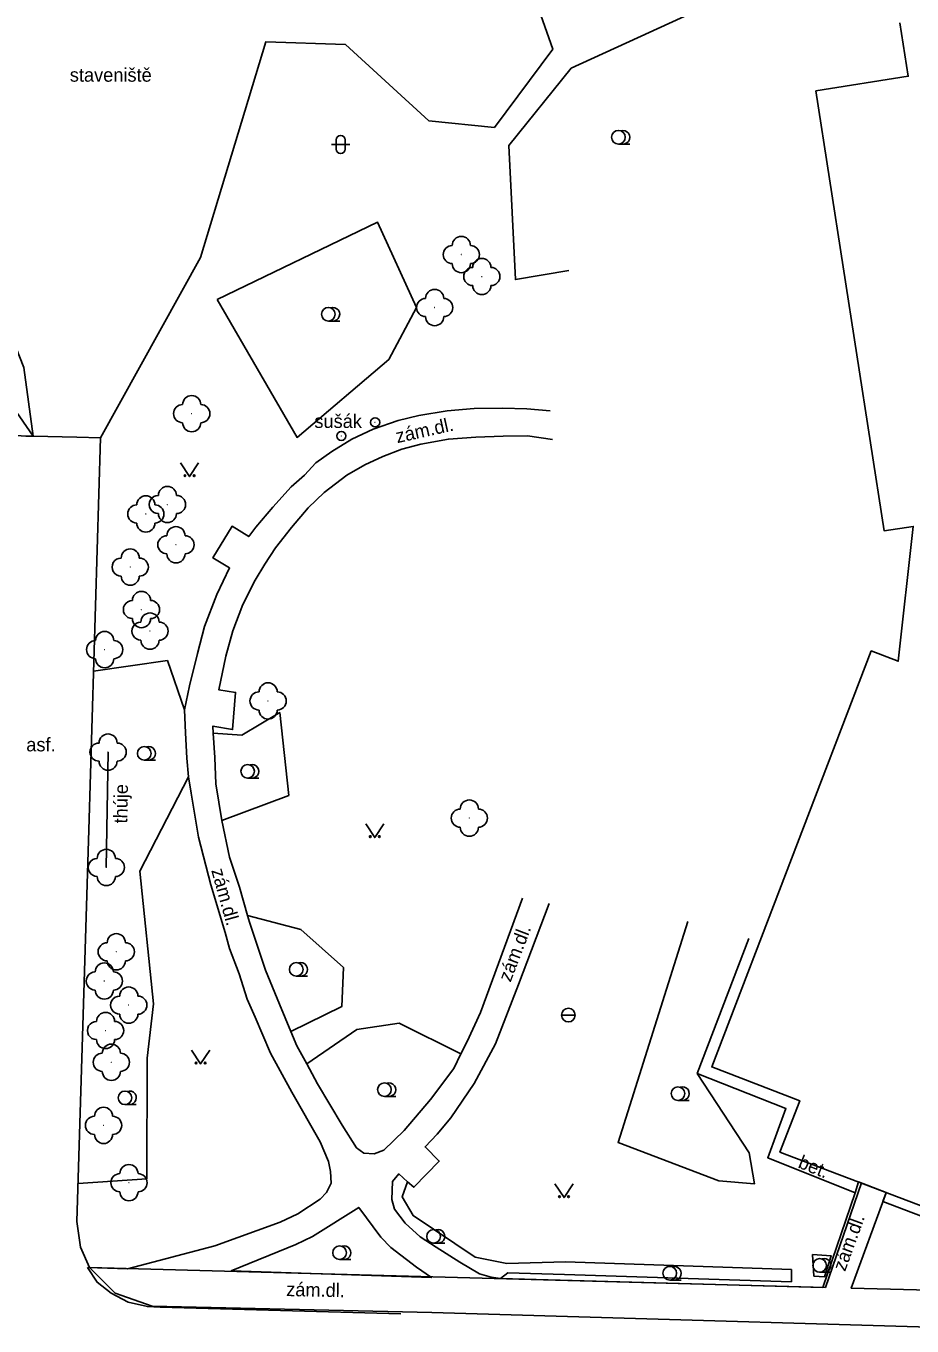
# Model space of a CAD drawing. Extents: x -584400 to -581602, y -1210894 to -1208793.
# Drawn here: x -582747.8 to -582698.9, y -1209957.3 to -1209885.6 of the extents above; entities that cross this region are included whole.
import ezdxf

# ---------------------------------------------------------------- set-up
doc = ezdxf.new("R2010")
doc.units = 0
for name, color, linetype in [('BUDOVY_MĚŘ', 7, 'Continuous'), ('POMOC_POPIS', 7, 'Continuous'), ('ROZHRANÍ_PLOCH', 7, 'Continuous'), ('VÝŠKOPIS', 7, 'Continuous'), ('ZELEŇ', 7, 'Continuous'), ('ZN_DOPLŇKOVÉ', 7, 'Continuous'), ('ZN_KULTUR', 7, 'Continuous')]:
    doc.layers.add(name, color=color, linetype=linetype)

msp = doc.modelspace()

# ---------------------------------------------------------------- linework, layer by layer
at = {"layer": 'BUDOVY_MĚŘ'}
for points in [[(-582688.59, -1209883.71), (-582688.07, -1209886.96), (-582683.44, -1209886.21), (-582679.67, -1209910.15), (-582680.11, -1209910.22), (-582679.82, -1209913.58), (-582679.75, -1209916.25), (-582680.55, -1209916.44), (-582681.08, -1209921.35), (-582680.32, -1209921.67), (-582680.94, -1209924.3), (-582681.99, -1209927.46), (-582681.57, -1209927.62), (-582690.3, -1209950.23), (-582694.69, -1209948.54), (-582695.81, -1209951.64), (-582706.2, -1209947.68), (-582705.11, -1209944.85), (-582709.96, -1209942.99), (-582701.17, -1209920.05), (-582699.68, -1209920.62), (-582698.85, -1209913.19), (-582700.45, -1209913.44), (-582704.22, -1209889.17)], [(-582704.22, -1209889.17), (-582699.13, -1209888.37), (-582699.59, -1209885.42)]]:
    msp.add_lwpolyline(points, dxfattribs=at)
at = {"layer": 'ROZHRANÍ_PLOCH'}
for points in [[(-582743.64, -1209908.31), (-582738.14, -1209898.36), (-582734.53, -1209886.47), (-582730.14, -1209886.62), (-582725.56, -1209890.82), (-582721.94, -1209891.19), (-582718.71, -1209886.88), (-582720.59, -1209881.55), (-582720.32, -1209873.3), (-582716.2, -1209870.3), (-582710.56, -1209867.68), (-582702.54, -1209865.54), (-582699, -1209870.36)], [(-582757.47, -1209885.68), (-582753.16, -1209892.91), (-582749.85, -1209899.43), (-582747.87, -1209904.42), (-582747.36, -1209908.22)], [(-582718.87, -1209906.82), (-582720.15, -1209906.71), (-582721.49, -1209906.66), (-582723.05, -1209906.68), (-582724.54, -1209906.82), (-582726.1, -1209907.08), (-582727.24, -1209907.34), (-582728.62, -1209907.83), (-582729.8, -1209908.37), (-582730.89, -1209909.05), (-582731.78, -1209909.69), (-582732.4, -1209910.37), (-582733.14, -1209911), (-582734.15, -1209912.13), (-582735.09, -1209913.22), (-582735.48, -1209913.75), (-582736.4, -1209913.18), (-582737.45, -1209914.92), (-582736.53, -1209915.48), (-582737.23, -1209916.94), (-582737.91, -1209918.7), (-582738.3, -1209920.2), (-582738.75, -1209921.98), (-582739.01, -1209923.3)], [(-582747.36, -1209908.22), (-582747.77, -1209908.21), (-582749.09, -1209908.12), (-582749.33, -1209915.59)], [(-582744.95, -1209908.27), (-582747.36, -1209908.22)], [(-582744.3, -1209929.91), (-582743.64, -1209908.31), (-582744.95, -1209908.27)], [(-582737.43, -1209924.59), (-582737.45, -1209924.2), (-582736.37, -1209924.39), (-582736.2, -1209922.34), (-582737.12, -1209922.2), (-582736.74, -1209920.35), (-582736.35, -1209918.94), (-582735.8, -1209917.5), (-582735.13, -1209916.16), (-582734.59, -1209915.27), (-582734, -1209914.37), (-582733.12, -1209913.25), (-582732.2, -1209912.16), (-582731.32, -1209911.31), (-582730.08, -1209910.37), (-582729.08, -1209909.79), (-582728.08, -1209909.33), (-582727.04, -1209908.93), (-582725.99, -1209908.66), (-582724.47, -1209908.37), (-582722.97, -1209908.26), (-582721.46, -1209908.22), (-582720.12, -1209908.19), (-582718.73, -1209908.39)], [(-582738.8, -1209926.99), (-582738.89, -1209925.97), (-582738.96, -1209924.57), (-582739.01, -1209923.3)], [(-582736.97, -1209929.41), (-582737.3, -1209927.38), (-582737.34, -1209925.92), (-582737.43, -1209924.59)], [(-582744.36, -1209954.05), (-582742.16, -1209954.11), (-582737.35, -1209952.85), (-582733.75, -1209951.54), (-582732.78, -1209951.08), (-582731.55, -1209950.27), (-582731.19, -1209949.91), (-582730.94, -1209949.4), (-582730.97, -1209948.75), (-582731.09, -1209948.21), (-582731.55, -1209947.11), (-582733.11, -1209944.38), (-582734.27, -1209942.23), (-582735.13, -1209940.24), (-582735.56, -1209939.26), (-582736.01, -1209937.85), (-582736.54, -1209936.45), (-582736.78, -1209935.58), (-582737.56, -1209932.94), (-582738.25, -1209930.32), (-582738.65, -1209927.89), (-582738.8, -1209926.99)], [(-582735.55, -1209934.63), (-582735.98, -1209933.08), (-582736.54, -1209931.42), (-582736.97, -1209929.41)], [(-582744.95, -1209951.51), (-582744.3, -1209929.91)], [(-582726.72, -1209949.32), (-582726.37, -1209949.62), (-582724.98, -1209948.18), (-582725.76, -1209947.4), (-582725.09, -1209946.69), (-582724.33, -1209945.79), (-582723.06, -1209943.9), (-582721.87, -1209941.71), (-582720.61, -1209938.44), (-582718.92, -1209933.97)], [(-582720.38, -1209933.68), (-582722.71, -1209939.99), (-582723.44, -1209941.58), (-582723.78, -1209942.26)], [(-582733.15, -1209941.04), (-582733.79, -1209939.53), (-582734.56, -1209937.65), (-582735.44, -1209935.01), (-582735.55, -1209934.63)], [(-582710.77, -1209943.35), (-582707.91, -1209935.91)], [(-582732.28, -1209942.82), (-582732.82, -1209941.83), (-582733.15, -1209941.04)], [(-582723.78, -1209942.26), (-582724.18, -1209943.07), (-582725.46, -1209944.79), (-582726.92, -1209946.5), (-582728.04, -1209947.58), (-582728.57, -1209947.78), (-582729.13, -1209947.75), (-582729.54, -1209947.44), (-582730.33, -1209946.2), (-582731.68, -1209943.91), (-582732.28, -1209942.82)], [(-582702.06, -1209949.93), (-582706.87, -1209947.99), (-582705.87, -1209945.27), (-582710.77, -1209943.35)], [(-582721.61, -1209954.66), (-582722.11, -1209954.57), (-582722.76, -1209954.39), (-582723.84, -1209953.75), (-582725.15, -1209952.92), (-582726.02, -1209952.35), (-582726.85, -1209951.6), (-582727.44, -1209950.83), (-582727.6, -1209950.3), (-582727.56, -1209949.31), (-582727.21, -1209948.89), (-582726.72, -1209949.32)], [(-582701.71, -1209949.37), (-582703.69, -1209955.14), (-582744.25, -1209954.04)], [(-582702.06, -1209949.93), (-582701.86, -1209949.33)], [(-582702.06, -1209949.93), (-582703.83, -1209955.14), (-582721.61, -1209954.66)], [(-582684.25, -1209955.64), (-582702.27, -1209955.19), (-582700.35, -1209949.93)], [(-582700.53, -1209950.41), (-582700.35, -1209949.91)], [(-582695.46, -1209952.34), (-582700.53, -1209950.41)], [(-582736.45, -1209954.23), (-582732.89, -1209952.77), (-582731.96, -1209952.34), (-582729.41, -1209950.73), (-582728.2, -1209952.37), (-582727.64, -1209952.94), (-582726.24, -1209954.02), (-582725.41, -1209954.6), (-582736.45, -1209954.23)], [(-582740.8, -1209956.17), (-582742.84, -1209955.46), (-582744.25, -1209954.04), (-582744.75, -1209952.92), (-582744.95, -1209951.51)], [(-582727.09, -1209956.6), (-582740.36, -1209956.23), (-582741.06, -1209956.2), (-582742.13, -1209955.95), (-582743.06, -1209955.46), (-582743.84, -1209954.86), (-582744.36, -1209954.05)], [(-582740.8, -1209956.17), (-582725.38, -1209956.53), (-582689.21, -1209957.59), (-582687.98, -1209957.62), (-582671.03, -1209958.14)]]:
    msp.add_lwpolyline(points, dxfattribs=at)
at = {"layer": 'VÝŠKOPIS'}
msp.add_lwpolyline([(-582755.21, -1209894.05), (-582754.02, -1209896.75), (-582750.32, -1209903.94), (-582747.36, -1209908.22)], dxfattribs=at)
at = {"layer": 'ZELEŇ'}
for points in [[(-582709.1, -1209883.98), (-582717.7, -1209887.93), (-582721.14, -1209892.18), (-582720.78, -1209899.58), (-582717.84, -1209899.08)], [(-582737.22, -1209900.68), (-582732.81, -1209908.28), (-582727.76, -1209903.98), (-582726.24, -1209901.12), (-582728.38, -1209896.42), (-582737.22, -1209900.68)], [(-582744.03, -1209921.16), (-582739.96, -1209920.58), (-582739.01, -1209923.3)], [(-582736.97, -1209929.41), (-582733.27, -1209928.02), (-582733.77, -1209923.45), (-582735.85, -1209924.7), (-582737.43, -1209924.59)], [(-582743.33, -1209931.99), (-582743.23, -1209925.63)], [(-582738.8, -1209926.99), (-582741.48, -1209932.2), (-582740.72, -1209939.5), (-582741.07, -1209942.51), (-582741.1, -1209949.15), (-582744.88, -1209949.41)], [(-582735.55, -1209934.63), (-582732.61, -1209935.41), (-582730.26, -1209937.5), (-582730.35, -1209939.66), (-582733.15, -1209941.04)], [(-582711.28, -1209934.97), (-582715.12, -1209947.16), (-582709.57, -1209949.27), (-582707.61, -1209949.44), (-582707.89, -1209947.73), (-582710.77, -1209943.35)], [(-582732.28, -1209942.82), (-582729.52, -1209940.93), (-582727.18, -1209940.58), (-582723.78, -1209942.26)], [(-582726.72, -1209949.32), (-582727.03, -1209950.15), (-582726.41, -1209951.18), (-582722.99, -1209953.48), (-582721.25, -1209953.82), (-582718.02, -1209953.73), (-582705.57, -1209954.16), (-582705.57, -1209954.83), (-582718.08, -1209954.43), (-582721.19, -1209954.33), (-582721.61, -1209954.66)], [(-582704.4, -1209953.32), (-582704.33, -1209954.52), (-582703.75, -1209954.56), (-582703.37, -1209953.41), (-582704.4, -1209953.32)]]:
    msp.add_lwpolyline(points, dxfattribs=at)
for centre in [(-582723.76, -1209898.2), (-582722.63, -1209899.41), (-582725.23, -1209901.12), (-582738.62, -1209906.97), (-582741.15, -1209912.5), (-582739.96, -1209911.98), (-582739.49, -1209914.2), (-582742.01, -1209915.43), (-582741.39, -1209917.77), (-582740.92, -1209918.96), (-582743.42, -1209919.98), (-582734.41, -1209922.81), (-582743.23, -1209925.63), (-582723.32, -1209929.27), (-582743.33, -1209931.99), (-582742.78, -1209936.64), (-582743.44, -1209938.25), (-582742.09, -1209939.58), (-582743.37, -1209940.98), (-582743.05, -1209942.73), (-582743.48, -1209946.21), (-582742.08, -1209949.37)]:
    msp.add_circle(centre, 0.0005, dxfattribs=at)
for centre, start, end in [((-582723.76, -1209897.7), 0, 179.99999), ((-582724.26, -1209898.2), 89.99999, 269.99999), ((-582723.26, -1209898.2), 270, 89.99999), ((-582723.76, -1209898.7), 179.99999, 359.99999), ((-582723.13, -1209899.41), 89.99999, 269.99999), ((-582722.63, -1209898.91), 0, 179.99999), ((-582722.13, -1209899.41), 270, 89.99999), ((-582725.23, -1209900.62), 360, 179.99999), ((-582722.63, -1209899.91), 179.99999, 359.99999), ((-582725.73, -1209901.12), 90, 269.99999), ((-582724.73, -1209901.12), 270, 90), ((-582725.23, -1209901.62), 180, 360), ((-582738.62, -1209906.47), 0, 179.99999), ((-582739.12, -1209906.97), 89.99999, 269.99999), ((-582738.12, -1209906.97), 270, 89.99999), ((-582738.62, -1209907.47), 179.99999, 359.99999), ((-582739.96, -1209911.48), 359.99998, 179.99998), ((-582741.15, -1209912), 0, 179.99999), ((-582740.46, -1209911.98), 89.99998, 269.99998), ((-582739.46, -1209911.98), 269.99998, 89.99997), ((-582741.65, -1209912.5), 89.99999, 269.99999), ((-582740.65, -1209912.5), 270, 89.99999), ((-582739.96, -1209912.48), 179.99998, 359.99997), ((-582741.15, -1209913), 179.99999, 359.99999), ((-582739.49, -1209913.7), 360, 179.99999), ((-582739.99, -1209914.2), 90, 269.99999), ((-582738.99, -1209914.2), 270, 90), ((-582742.01, -1209914.93), 359.99998, 179.99998), ((-582739.49, -1209914.7), 180, 360), ((-582742.51, -1209915.43), 89.99998, 269.99998), ((-582741.51, -1209915.43), 269.99998, 89.99997), ((-582742.01, -1209915.93), 179.99998, 359.99997), ((-582741.39, -1209917.27), 359.99998, 179.99998), ((-582741.89, -1209917.77), 89.99998, 269.99998), ((-582740.89, -1209917.77), 269.99998, 89.99997), ((-582741.39, -1209918.27), 179.99998, 359.99997), ((-582740.92, -1209918.46), 359.99998, 179.99998), ((-582743.42, -1209919.48), 360, 179.99999), ((-582741.42, -1209918.96), 89.99998, 269.99998), ((-582740.42, -1209918.96), 269.99998, 89.99997), ((-582743.92, -1209919.98), 90, 269.99999), ((-582742.92, -1209919.98), 270, 90), ((-582740.92, -1209919.46), 179.99998, 359.99997), ((-582743.42, -1209920.48), 180, 360), ((-582734.41, -1209922.31), 360, 179.99999), ((-582734.91, -1209922.81), 90, 269.99999), ((-582733.91, -1209922.81), 270, 90), ((-582734.41, -1209923.31), 180, 360), ((-582743.23, -1209925.13), 360, 179.99999), ((-582743.73, -1209925.63), 90, 269.99999), ((-582742.73, -1209925.63), 270, 90), ((-582743.23, -1209926.13), 180, 360), ((-582723.32, -1209928.77), 360, 179.99999), ((-582723.82, -1209929.27), 90, 269.99999), ((-582722.82, -1209929.27), 270, 90), ((-582723.32, -1209929.77), 180, 360), ((-582743.33, -1209931.49), 359.99998, 179.99998), ((-582743.83, -1209931.99), 89.99998, 269.99998), ((-582742.83, -1209931.99), 269.99998, 89.99997), ((-582743.33, -1209932.49), 179.99998, 359.99997), ((-582743.28, -1209936.64), 89.99999, 269.99999), ((-582742.78, -1209936.14), 0, 179.99999), ((-582742.28, -1209936.64), 270, 89.99999), ((-582743.44, -1209937.75), 359.99998, 179.99998), ((-582742.78, -1209937.14), 179.99999, 359.99999), ((-582743.94, -1209938.25), 89.99998, 269.99998), ((-582742.94, -1209938.25), 269.99998, 89.99997), ((-582743.44, -1209938.75), 179.99998, 359.99997), ((-582742.59, -1209939.58), 89.99998, 269.99998), ((-582742.09, -1209939.08), 359.99998, 179.99998), ((-582741.59, -1209939.58), 269.99998, 89.99997), ((-582743.87, -1209940.98), 89.99998, 269.99998), ((-582743.37, -1209940.48), 359.99998, 179.99998), ((-582742.87, -1209940.98), 269.99998, 89.99997), ((-582742.09, -1209940.08), 179.99998, 359.99997), ((-582743.37, -1209941.48), 179.99998, 359.99997), ((-582743.05, -1209942.23), 360, 179.99999), ((-582743.55, -1209942.73), 90, 269.99999), ((-582742.55, -1209942.73), 270, 90), ((-582743.05, -1209943.23), 180, 360), ((-582743.48, -1209945.71), 360, 179.99999), ((-582743.98, -1209946.21), 90, 269.99999), ((-582742.98, -1209946.21), 270, 90), ((-582743.48, -1209946.71), 180, 360), ((-582742.08, -1209948.87), 360, 179.99999), ((-582742.58, -1209949.37), 90, 269.99999), ((-582741.58, -1209949.37), 270, 90), ((-582742.08, -1209949.87), 180, 360)]:
    msp.add_arc(centre, 0.5, start, end, dxfattribs=at)
at = {"layer": 'ZN_DOPLŇKOVÉ'}
msp.add_line((-582718.235, -1209940.13), (-582717.485, -1209940.13), dxfattribs=at)
msp.add_lwpolyline([(-582700.35, -1209949.91), (-582701.86, -1209949.33)], dxfattribs=at)
for centre, radius in [((-582728.51, -1209907.451), 0.25), ((-582728.51, -1209907.451), 0.0005), ((-582730.37, -1209908.199), 0.25), ((-582730.37, -1209908.199), 0.0005), ((-582717.86, -1209940.13), 0.375)]:
    msp.add_circle(centre, radius, dxfattribs=at)
at = {"layer": 'ZN_KULTUR'}
for p, q in [((-582730.91, -1209892.13), (-582729.91, -1209892.13)), ((-582730.66, -1209892.38), (-582730.66, -1209891.88)), ((-582730.16, -1209892.38), (-582730.16, -1209891.88)), ((-582715.1, -1209892.105), (-582714.475, -1209892.105)), ((-582731.09, -1209901.865), (-582730.465, -1209901.865)), ((-582741.24, -1209926.075), (-582740.615, -1209926.075)), ((-582735.54, -1209927.065), (-582734.915, -1209927.065)), ((-582732.86, -1209937.985), (-582732.235, -1209937.985)), ((-582728, -1209944.615), (-582727.375, -1209944.615)), ((-582742.3, -1209945.065), (-582741.675, -1209945.065)), ((-582711.82, -1209944.835), (-582711.195, -1209944.835)), ((-582725.29, -1209952.705), (-582724.665, -1209952.705)), ((-582730.47, -1209953.605), (-582729.845, -1209953.605)), ((-582712.27, -1209954.735), (-582711.645, -1209954.735)), ((-582704.01, -1209954.305), (-582703.385, -1209954.305))]:
    msp.add_line(p, q, dxfattribs=at)
for points in [[(-582739.24, -1209909.69), (-582738.74, -1209910.44), (-582738.24, -1209909.69)], [(-582729.03, -1209929.59), (-582728.53, -1209930.34), (-582728.03, -1209929.59)], [(-582738.63, -1209942.07), (-582738.13, -1209942.82), (-582737.63, -1209942.07)], [(-582718.6, -1209949.44), (-582718.1, -1209950.19), (-582717.6, -1209949.44)]]:
    msp.add_lwpolyline(points, dxfattribs=at)
for centre, radius in [((-582715.1, -1209891.73), 0.375), ((-582731.09, -1209901.49), 0.375), ((-582738.99, -1209910.39), 0.05), ((-582738.49, -1209910.39), 0.05), ((-582741.24, -1209925.7), 0.375), ((-582735.54, -1209926.69), 0.375), ((-582728.78, -1209930.29), 0.05), ((-582728.28, -1209930.29), 0.05), ((-582732.86, -1209937.61), 0.375), ((-582738.38, -1209942.77), 0.05), ((-582737.88, -1209942.77), 0.05), ((-582728, -1209944.24), 0.375), ((-582711.82, -1209944.46), 0.375), ((-582742.3, -1209944.69), 0.375), ((-582718.35, -1209950.14), 0.05), ((-582717.85, -1209950.14), 0.05), ((-582725.29, -1209952.33), 0.375), ((-582730.47, -1209953.23), 0.375), ((-582712.27, -1209954.36), 0.375), ((-582704.01, -1209953.93), 0.375)]:
    msp.add_circle(centre, radius, dxfattribs=at)
for centre, radius, start, end in [((-582730.41, -1209891.88), 0.25, 0, 179.99999), ((-582714.85, -1209891.73), 0.375, 249.49437, 109.04743), ((-582730.41, -1209892.38), 0.25, 179.99999, 359.99999), ((-582730.84, -1209901.49), 0.375, 249.49437, 109.04743), ((-582740.99, -1209925.7), 0.375, 249.49437, 109.04743), ((-582735.29, -1209926.69), 0.375, 249.49437, 109.04743), ((-582732.61, -1209937.61), 0.375, 249.49437, 109.04743), ((-582727.75, -1209944.24), 0.375, 249.49437, 109.04743), ((-582711.57, -1209944.46), 0.375, 249.49437, 109.04743), ((-582742.05, -1209944.69), 0.375, 249.49437, 109.04743), ((-582725.04, -1209952.33), 0.375, 249.49437, 109.04743), ((-582730.22, -1209953.23), 0.375, 249.49437, 109.04743), ((-582712.02, -1209954.36), 0.375, 249.49437, 109.04743), ((-582703.76, -1209953.93), 0.375, 249.49437, 109.04743)]:
    msp.add_arc(centre, radius, start, end, dxfattribs=at)

# ---------------------------------------------------------------- texts
at = {"layer": 'POMOC_POPIS'}
for s, p in [('staveniště', (-582745.34, -1209888.67)), ('sušák', (-582731.86, -1209907.76)), ('asf.', (-582747.74, -1209925.59))]:
    msp.add_text(s, height=0.75, dxfattribs=at).set_placement(p)
for s, rotation, p in [('zám.dl.', 12.6112, (-582727.29, -1209908.6)), ('zám.dl.', 285.60714, (-582737.55, -1209932.15)), ('zám.dl.', 69.10845, (-582721.05, -1209938.35)), ('bet.', 338.0345, (-582705.25, -1209948.52)), ('zám.dl.', 69.99762, (-582702.61, -1209954.3)), ('zám.dl.', 358.85269, (-582733.42, -1209955.62))]:
    msp.add_text(s, height=0.75, rotation=rotation, dxfattribs=at).set_placement(p)
at = {"layer": 'ZELEŇ'}
msp.add_text('thúje', height=0.75, rotation=89.09918, dxfattribs=at).set_placement((-582742.17, -1209929.57))

doc.saveas('drawing.dxf')
